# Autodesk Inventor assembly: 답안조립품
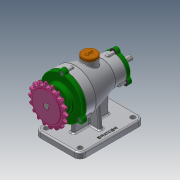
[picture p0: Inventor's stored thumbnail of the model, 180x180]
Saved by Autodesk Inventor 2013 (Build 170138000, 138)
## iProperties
Created: 2020-03
Part Number: 답안조립품
Document SubType Name: Assembly
Designer: user
Author: user
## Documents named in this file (15)
- C:\Users\user\Desktop\700306V1012\답안조립품.iam
- C:\Users\user\Desktop\700306V1012\개스킷 A.ipt
- C:\Users\user\Desktop\700306V1012\개스킷 B.ipt
- C:\Users\user\Desktop\700306V1012\뒤커버.ipt
- C:\Users\user\Desktop\700306V1012\마개.ipt
- C:\Users\user\Desktop\700306V1012\베어링 6200.ipt
- C:\Users\user\Desktop\700306V1012\베어링 6203.ipt
- C:\Users\user\Desktop\700306V1012\본체.ipt
- C:\Users\user\Desktop\700306V1012\볼트 M5.ipt
- C:\Users\user\Desktop\700306V1012\스프로킷.ipt
- C:\Users\user\Desktop\700306V1012\앞커버.ipt
- C:\Users\user\Desktop\700306V1012\오일 실 10 20 7.ipt
- C:\Users\user\Desktop\700306V1012\오일 실 17 30 8.ipt
- C:\Users\user\Desktop\700306V1012\축.ipt
- C:\Users\user\Desktop\700306V1012\키 4x4x14.ipt
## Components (2 placed, 2 different names)
1. 개스킷 A:1
2. 개스킷 B:1
